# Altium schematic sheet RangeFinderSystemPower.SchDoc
size A; DocumentNumber: 6; SheetNumber: 6; SheetTotal: 6
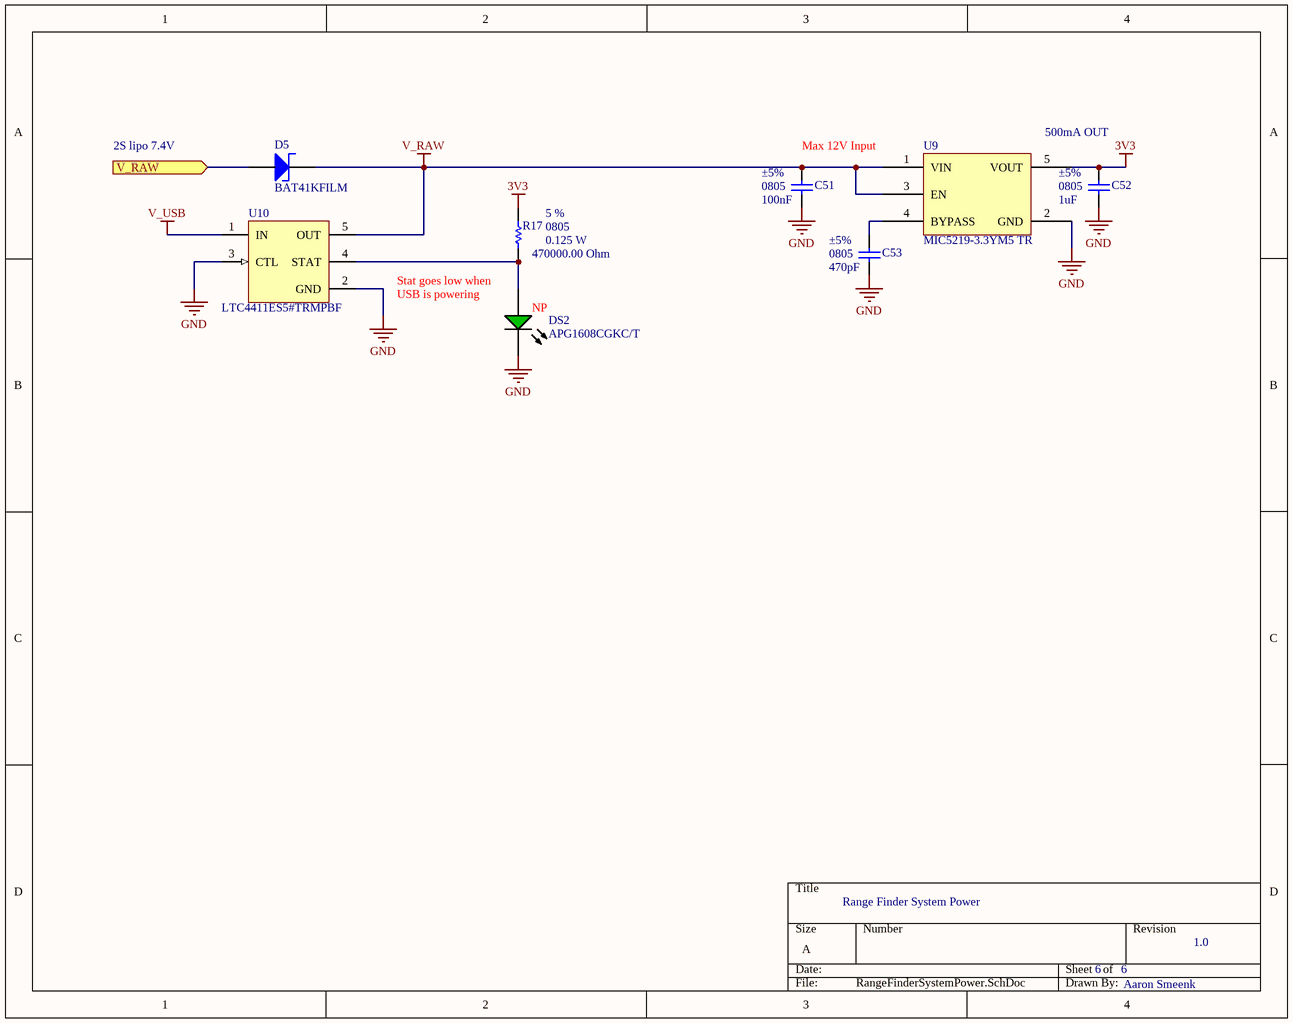
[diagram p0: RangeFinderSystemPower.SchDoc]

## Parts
C51  value 100nF  Tolerance: ±5%  Case-EIA: 0805  [CAPC0805(2012)100_L]  (hidden comment: CAP 100nF 6.3V 0805(2012))
C52  value 1uF  Tolerance: ±5%  Case-EIA: 0805  [CAPC0805(2012)100_M]  (hidden comment: CAP 1uF 6.3V 0805(2012))
C53  value 470pF  Case-EIA: 0805  Tolerance: ±5%  [CAPC0805(2012)100_L]  (hidden comment: CAP 470pF 6.3V 0805(2012))
D5  BAT41KFILM  [BAT41KFILM]
DS2  APG1608CGKC/T  [KING-LED0603-25-GREEN_V]
R17  value 470000.00 Ohm  Power: 0.125 W  Tolerance: 5 %  Case-EIA: 0805  [RESC0805(2012)_M]  (hidden comment: 470K 5% 0805(2012))
U9  MIC5219-3.3YM5 TR  [MIC5219-3.3YM5 TR--SOT95P280X145-5N]
U10  LTC4411ES5#TRMPBF  [LT-S5-5-TSOT-23_N]

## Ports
V_RAW (in)

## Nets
3V3: C52.2 R17.2 U9.5(VOUT)
GND: C51.1 C52.1 C53.1 DS2.2(K) U9.2(GND) U10.2(GND) U10.3(CTL)
V_RAW: C51.2 D5.1 U9.1(VIN) U9.3(EN) U10.5(OUT)
V_USB: U10.1(IN)
V_RAW: D5.2 ; port V_RAW  [a separate net that carries the same name]
NetC53_2: C53.2 U9.4(BYPASS)
NetDS2_1: DS2.1(A) R17.1 U10.4(STAT)

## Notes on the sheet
- 2S lipo 7.4V
- (near C51) Max 12V Input
- 500mA OUT
- Stat goes low when
- USB is powering
- (near DS2) NP
- Range Finder System Power
- 6
- 1.0
- Aaron Smeenk

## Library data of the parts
C51 = CMP-1036-04390-1: CAP 100nF 6.3V ±5% 0805 (2012 Metric) Thickness 1mm SMD; Case-Metric: 2012
C52 = CMP-1036-04730-1: CAP 1uF 6.3V ±5% 0805 (2012 Metric) Thickness 1mm SMD; Case-Metric: 2012
C53 = CMP-1036-02639-1: CAP 470pF 6.3V ±5% 0805 (2012 Metric) Thickness 1mm SMD; Case-Metric: 2012
D5 = BAT41KFILM: DIODE SCHOTTKY 100V 200MA SOD523; Current - Average Rectified (Io): 200mA (DC); Voltage - Forward (Vf) (Max) @ If: 1V @ 200mA; Speed: Small Signal =< 200mA (Io), Any Speed; Current - Reverse Leakage @ Vr: 100nA @ 50V; Capacitance @ Vr, F: 10pF @ 1V, 1MHz
DS2 = CMP-0239-00001-1: LED, SMT, 0603(1608), 0.25mm Thickness, Green; Forward Current: 30 mA; Reverse Voltage: 5 V; Power Dissipation: 78 mW; Packing: Reel
R17 = CMP-1013-00138-1: 470K 0.125W 5% 0805 (2012 Metric)  SMD; Case-Metric: 2012
U9 = MIC5219-3.3YM5 TR: IC REG LDO 3.3V 0.5A SOT23-5
U10 = CMP-0479-00414-1: Integrated Switch: Replaces Power Supply OR, 2.6 to 5.5 V Vin, 5-pin SOT23 (S5-5), -40 to 85 degC, Pb-Free, Mini Tape and Reel; Manufacturer: Linear Technology; Ideal Diode: Single, Internal, P-Channel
